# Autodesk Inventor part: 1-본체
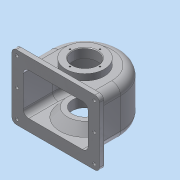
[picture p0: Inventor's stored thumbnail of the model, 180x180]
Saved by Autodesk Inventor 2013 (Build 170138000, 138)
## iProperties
Created: 2015-09
Part Number: 1-본체
Material: 알루미늄 6061
Document SubType Name: Modeling
Designer: ST4
Density: 2.71 g/cm^3
Mass: 678.469 g
Surface Area: 907.543 cm^2
Volume: 250.357 cm^3
Author: ST4
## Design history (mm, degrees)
sketch "스케치1"
  geometry: L1 (-57, -47)-(57, -47); L2 (-57, 0)-(-57, -47); L3 (57, 0)-(57, -47); A1 r 57 centre (0, 0) between (32.249, -47) and (-32.249, -47); 2 further points
  constraints: 6 end point, 4 point on circle, 2 point on line, 2 tangent, 1 centre point, 1 coincident, 1 horizontal, 1 midpoint, 1 parallel, 1 vertical, 1 vertical alignment
  dimensions: "d0" = 114 diameter of A1; "d5" = 47 distance from line of L1 point (0, 0)
extrude "돌출1" new body sketch "스케치1" stored distance "d6" = 77; taper "d7" = 0 deg
feature "쉘1" dims "d8" = 5
sketch "스케치2"
  geometry: L1 (5, -5)-(109, -5) reference; L2 (0, 0)-(114, 0) reference; L3 (0, -77)-(0, 0) reference; L4 (114, -77)-(0, -77) reference; L5 (114, -77)-(114, 0) reference; L6 (-13, 13.5)-(127, 13.5); L7 (127, 13.5)-(127, -90.5); L8 (127, -90.5)-(-13, -90.5); L9 (-13, -90.5)-(-13, 13.5); 3 further points
  constraints: 8 end point, 2 midpoint, 2 parallel, 1 horizontal, 1 horizontal alignment, 1 perpendicular, 1 vertical alignment
  dimensions: "d9" = 104 distance of L6.end L7.end; "d11" = 140 distance of L6.start L6.end
extrude "돌출2" join sketch "스케치2" distance "d12" = 7; taper "d13" = 0 deg
fillet "모깎기1" dims "d20" = 9
fillet "모깎기2" dims "d21" = 14
sketch "스케치6"
  geometry: C1 r 31 at (0, 0); A1 r 43 centre (0, 0) between (43, 0) and (-43, 0) reference
  constraints: 1 centre point, 1 coincident
  dimensions: "d32" = 62 diameter of C1
extrude "돌출3" join sketch "스케치6" distance "d34" = 10; taper "d35" = 0 deg
sketch "스케치7"
  geometry: C1 r 31 at (0, 0) reference; C2 r 20 at (0, 0)
  constraints: 1 centre point, 1 coincident
  dimensions: "d36" = 40 diameter of C2
extrude "돌출4" cut sketch "스케치7" stored distance "d38" = 10; taper "d39" = 0 deg
sketch "스케치15"
  geometry: L1 (0, -100.972)-(0, 100.972); L2 (43, -38.5)-(0, -38.5) reference; L3 (0, -33.5)-(43, -33.5) reference; L4 (-0.016, -35.5)-(36.309, -35.5); L5 (0, -19.5)-(28, -19.5); L6 (28, -19.5)-(39.747, -33.5); L7 (39.747, -33.5)-(0, -33.5); L8 (0, -33.5)-(0, -19.5); 2 further points
  constraints: 12 end point, 2 parallel, 2 point on line, 1 coincident, 1 collinear, 1 midpoint, 1 vertical
  dimensions: "d66" = 3 distance between parallel lines of L4 L2; "d71" = 56 diameter of L5.end L1; "d72" = 16 distance between parallel lines of L5 L4; "d73" = 50 deg angle of L5 L6
revolve "회전4" sketch "스케치15" stored, may be unused: angle "d74" = 90 deg
sketch "스케치16"
  geometry: L1 (43, -38.5)-(0, -38.5) reference; L2 (-40, -38.5)-(0, -38.5) reference; L3 (0, -72.766)-(0, 72.766); L4 (0, 24.5)-(0, -24.5) reference; L5 (37.416, -38.5)-(33, -33.237); L6 (0, -35.5)-(33, -35.5); L7 (28, -19.5)-(39.747, -33.5) reference; L8 (33, -35.5)-(33, -33.237); L9 (0, -38.5)-(37.416, -38.5); L10 (0, -38.5)-(0, -35.5); 2 further points
  constraints: 12 end point, 4 perpendicular, 3 point on line, 2 midpoint, 1 horizontal, 1 parallel
  dimensions: "d75" = 3 distance between parallel lines of L6 L1; "d76" = 5 distance between parallel lines of L7 L5; "d77" = 66 diameter of L8 L3
revolve "회전5" sketch "스케치16" stored, may be unused: angle "d78" = 90 deg
sketch "스케치17"
  geometry: C1 r 33 at (0, 0) reference; C2 r 20 at (0, 0)
  constraints: 1 centre point, 1 coincident
  dimensions: "d79" = 40 diameter of C2
extrude "돌출7" cut sketch "스케치17" distance "d81" = 16; taper "d82" = 0 deg
node "작업 평면2"
sketch "스케치18"
  geometry: C1 r 6 at (0, 0); 1 further point
  constraints: 1 centre point, 1 coincident
  dimensions: "d84" = 12 diameter of C1
extrude "돌출8" join sketch "스케치18" stored distance "d86" = 16; taper "d87" = 10 deg
sketch "스케치19"
  geometry: C1 r 6 at (0, 0) reference; 1 further point
  constraints: 1 coincident
hole "구멍1" sketch "스케치19" at (0, 0) diameter "d88" = 4.459; stored, may be unused: countersink angle "d92" = 90 deg, drill point angle "d94" = 118 deg; dims "d89" = 6, "d90" = 4, "d91" = 2, "d93" = 8
fillet "모깎기3" dims "d95" = 3
sketch "스케치20"
  geometry: C1 r 2.5 at (119, 82.5); C2 r 2.5 at (-5, 82.5); C3 r 2.5 at (-5, 38.5); C4 r 2.5 at (119, 38.5); C5 r 2.5 at (119, -5.5); C6 r 2.5 at (-5, -5.5); 1 further point
  constraints: 6 centre point, 5 equal radius, 4 horizontal alignment, 4 vertical alignment
  dimensions: "d96" = 44 distance of C4.centre C1.centre; "d99" = 124 distance of C1.centre C2.centre; "d100" = 62 horizontal distance of point (57, 38.5) C2.centre; "d102" = 44 distance of C5.centre C4.centre; "d103" = 5 diameter of C4
extrude "돌출9" cut sketch "스케치20" stored distance "d104" = 16; taper "d105" = 0 deg
sketch "스케치21"
  geometry: C1 r 20 at (0, 0) reference; 1 further point
  constraints: 1 vertical alignment
  dimensions: "d106" = 24 distance of C1.centre point (0, 24)
hole "구멍2" sketch "스케치21" at (0, 24) diameter "d107" = 2.459; stored, may be unused: countersink angle "d111" = 90 deg, drill point angle "d113" = 118 deg; dims "d108" = 6, "d109" = 4, "d110" = 2, "d112" = 8
sketch "스케치22"
  geometry: C1 r 20 at (0, 0) reference; 1 further point
  constraints: 1 vertical alignment
  dimensions: "d117" = 28 distance of C1.centre point (0, 28)
hole "구멍3" sketch "스케치22" at (0, 28) diameter "d118" = 2.459; stored, may be unused: countersink angle "d122" = 90 deg, drill point angle "d124" = 118 deg; dims "d119" = 7, "d120" = 4, "d121" = 2, "d123" = 9
sketch "스케치23"
  geometry: L1 (0, 40)-(-49, 40) reference; L2 (-76.5, -7)-(27.5, -7) reference; 3 further points
  constraints: 1 midpoint, 1 vertical alignment, 1 other
  dimensions: "d128" = 30 distance from line of L2 point (-24.5, 23)
feature "엠보싱1" sketch "스케치23" dims "d0" = 114, "d5" = 47, "d129" = 0.5, "d130" = 0
fillet "모깎기4" dims "d131" = 1
fillet "모깎기5" dims "d132" = 7
chamfer "모따기1" distance "d133" = 1; stored, may be unused: second distance "d134" = 2, angle "d135" = 45 deg
fillet "모깎기6" dims "d136" = 0.5
fillet "모깎기7" dims "d137" = 3
node "솔리드1"
pattern_circular "원형 패턴1" dims angle "d115" = 360 deg
pattern_circular "원형 패턴2" dims angle "d126" = 360 deg
other parameters: "d51" = 66, "d83" = 63
